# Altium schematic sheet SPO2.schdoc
size 297 x 209 mm; Symbol: Drawing-Symbol_A4; Company: 嘉立创EDA; Version: V1.0; Page Size: A4; @Project Name: OpenECG; @Update Date: 2026-05-02; @Create Date: 2026-05-02; Device: Drawing-Symbol_A4; @Board Name: Board2; @Page Name: P1; @Create Time: 22:49:49; @Page Count: 1; @Page No: 1; @Schematic Name: Schematic5; @Update Time: 22:49:49; @Assembly Variant: Basic; Border: 1; Title Block Position: 3; Size: A4; Width: 1170; Height: 825; Region Start: 1; X Region Count: 6; Y Region Count: 4; Blade Width: 10
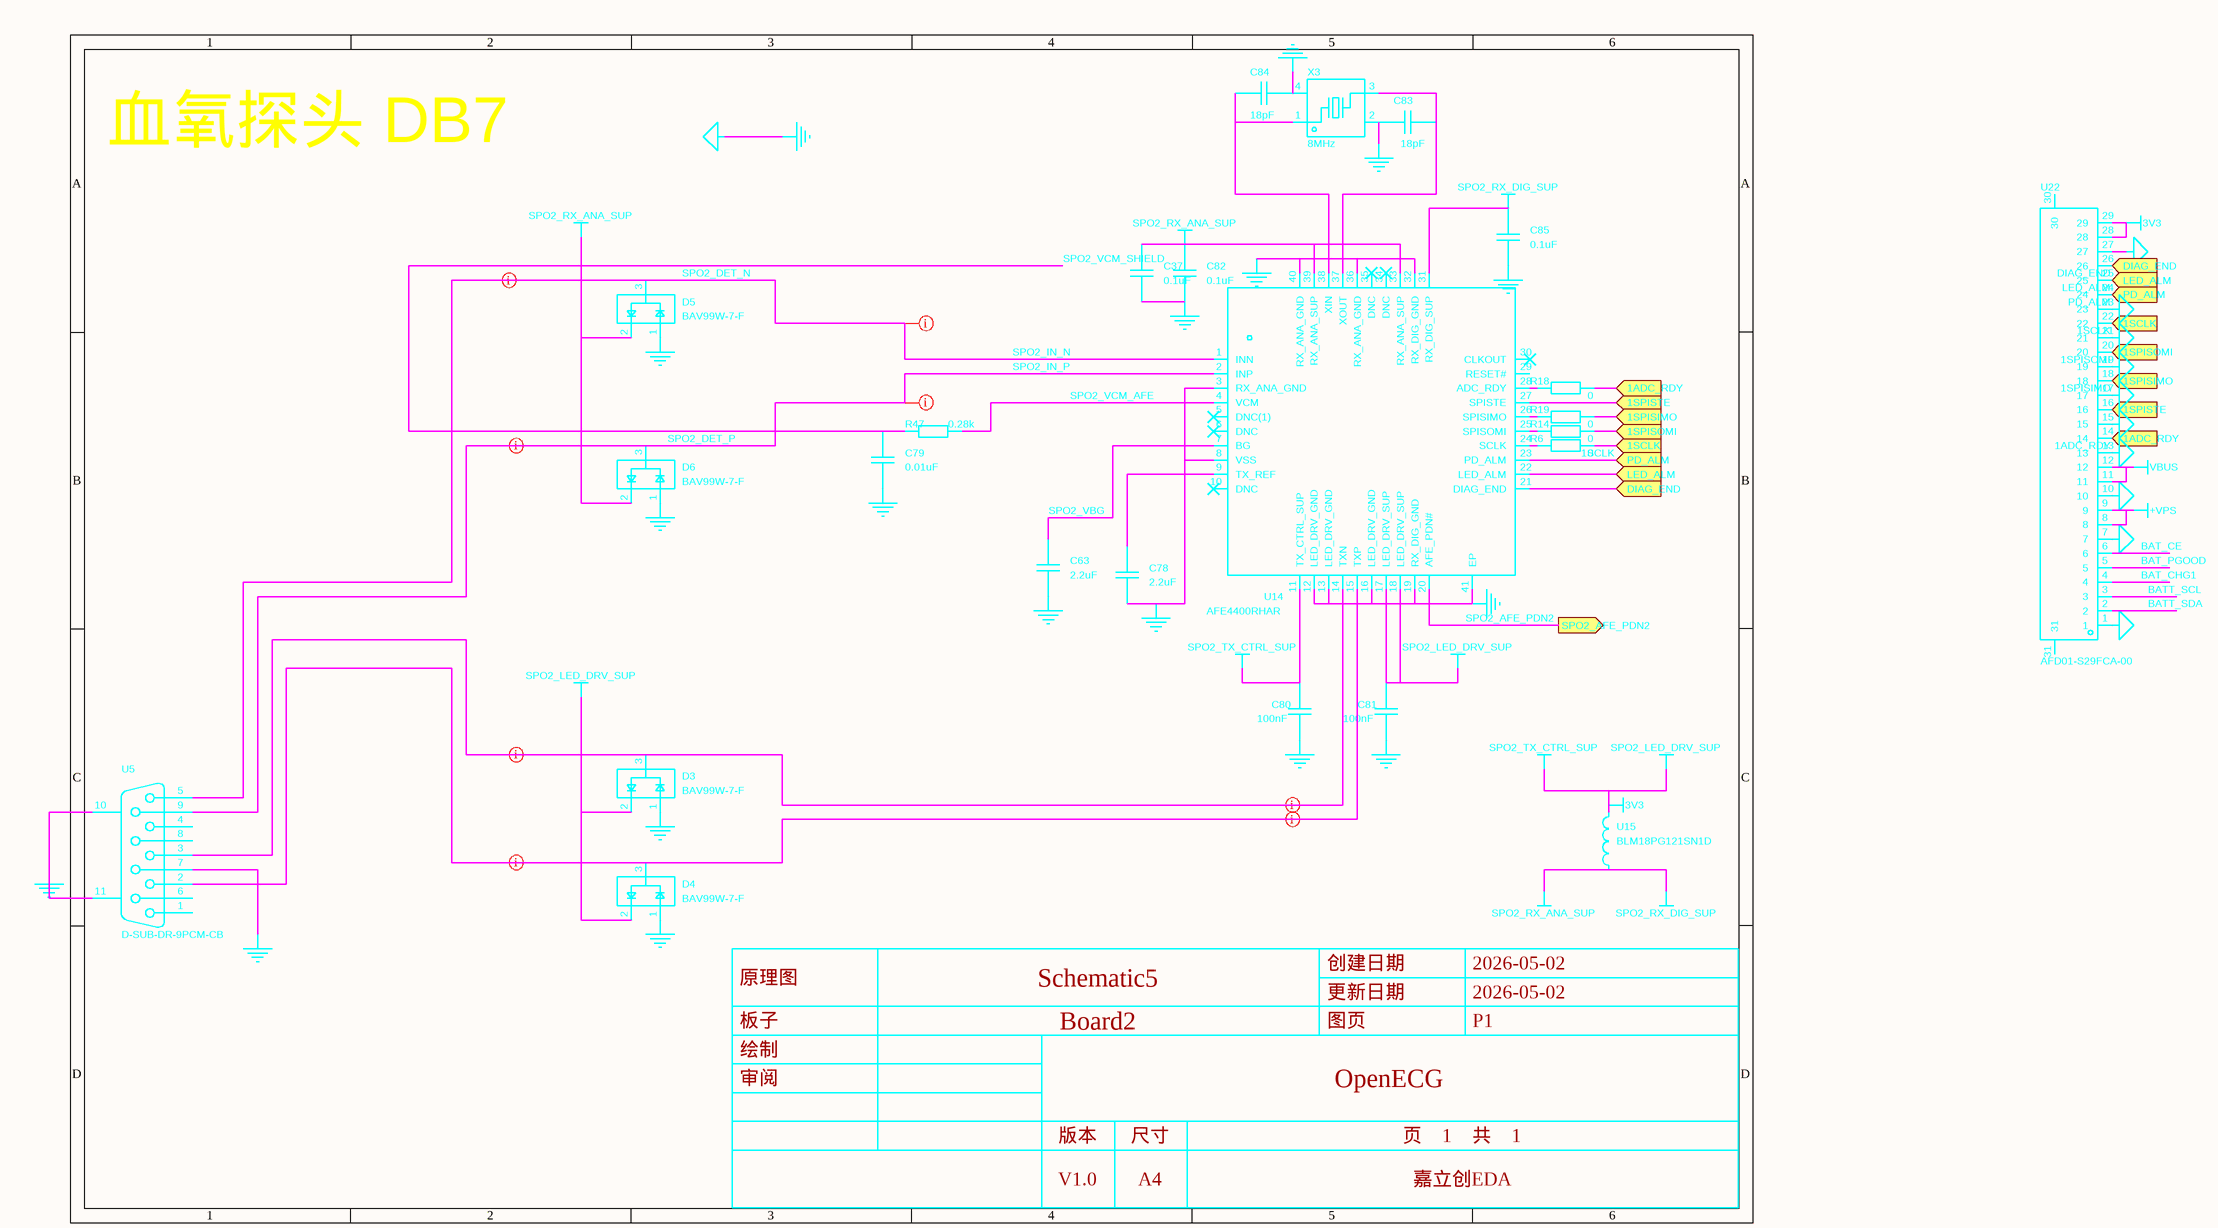
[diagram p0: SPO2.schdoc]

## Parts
C37  0.1uF  [R0603]
C63  2.2uF  [R0402]
C78  2.2uF  [R0402]
C79  0.01uF  [R0402]
C80  100nF  [C0603]
C81  100nF  [C0603]
C82  0.1uF  [R0603]
C83  18pF  [C0603]
C84  18pF  [C0603]
C85  0.1uF  [R0402]
D3  BAV99W-7-F  [SOT-323_L2.0-W1.3-P1.30-LS2.1-BR]
D4  BAV99W-7-F  [SOT-323_L2.0-W1.3-P1.30-LS2.1-BR]
D5  BAV99W-7-F  [SOT-323_L2.0-W1.3-P1.30-LS2.1-BR]
D6  BAV99W-7-F  [SOT-323_L2.0-W1.3-P1.30-LS2.1-BR]
R6  0  [R0603]
R14  0  [R0603]
R18  0  [R0603]
R19  0  [R0603]
R47  0.28k  [R0402]
U5  D-SUB-DR-9PCM-CB  [DB9-TH_D-SUB-DR-9PCM-CB]
U14  AFE4400RHAR  [VQFN-40_L6.0-W6.0-P0.50-TL-EP4.2]
U15  BLM18PG121SN1D  [R0402]
U22  AFD01-S29FCA-00  [FPC-SMD_29P-P0.50_JS_AFD01-S29FCA-00]
X3  8MHz  [CRYSTAL-SMD_4P-L3.2-W2.5-BL-1]

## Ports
1ADC_RDY (in), 1SCLK (in), 1SPISIMO (in), 1SPISOMI (in), 1SPISTE (in), DIAG_END (in), LED_ALM (in), PD_ALM (in), SPO2_AFE_PDN2 (out)

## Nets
3V3: C80.2 C81.2 D3.2 D4.2 U14.11(TX_CTRL_SUP) U14.17(LED_DRV_SUP) U14.18(LED_DRV_SUP) U15.2 U22.28 U22.29  [also labelled SPO2_LED_DRV_SUP, SPO2_TX_CTRL_SUP]
+VPS: U22.8 U22.9
AGND: C37.1 C63.1 C78.1 C79.1 C80.1 C81.1 C82.1 C83.1 C84.2 C85.1 D3.1 D4.1 D5.1 D6.1 U5.7 U5.10(MH1) U5.11(MH2) U14.3(RX_ANA_GND) U14.8(VSS) U14.12(LED_DRV_GND) U14.13(LED_DRV_GND) U14.16(LED_DRV_GND) U14.19(RX_DIG_GND) U14.32(RX_DIG_GND) U14.36(RX_ANA_GND) U14.40(RX_ANA_GND) U14.41(EP) U22.1 U22.7 U22.10 U22.13 U22.15 U22.17 U22.19 U22.21 U22.23 U22.27 X3.2(GND) X3.4(GND)  [also labelled GND]
SPO2_RX_ANA_SUP: C37.2 C82.2 C85.2 D5.2 D6.2 U14.31(RX_DIG_SUP) U14.33(RX_ANA_SUP) U14.39(RX_ANA_SUP) U15.1  [also labelled SPO2_RX_DIG_SUP]
VBUS: U22.11 U22.12
1ADC_RDY: R18.2 U22.14 ; port 1ADC_RDY
1SCLK: R6.2 U22.22 ; port 1SCLK
1SPISIMO: R19.2 U22.18 ; port 1SPISIMO
1SPISOMI: R14.2 U22.20 ; port 1SPISOMI
1SPISTE: U14.27(SPISTE) U22.16 ; port 1SPISTE
BAT_CE: U22.6
BAT_CHG1: U22.4
BAT_PGOOD: U22.5
BATT_SCL: U22.3
BATT_SDA: U22.2
DIAG_END: U14.21(DIAG_END) U22.26 ; port DIAG_END
LED_ALM: U14.22(LED_ALM) U22.25 ; port LED_ALM
PD_ALM: U14.23(PD_ALM) U22.24 ; port PD_ALM
SPO2_AFE_PDN2: U14.20(AFE_PDN#) ; port SPO2_AFE_PDN2
SPO2_DET_N: D5.3 U5.5 U14.1(INN)  [also labelled SPO2_IN_N]
SPO2_DET_P: D6.3 U5.9 U14.2(INP)  [also labelled SPO2_IN_P]
SPO2_VBG: C63.2 U14.7(BG)
SPO2_VCM_AFE: R47.2 U14.4(VCM)
SPO2_VCM_SHIELD: C79.2 R47.1
NetC78_2: C78.2 U14.9(TX_REF)
NetC83_2: C83.2 U14.37(XOUT) X3.3
NetC84_1: C84.1 U14.38(XIN) X3.1
NetD3_3: D3.3 U5.3 U14.14(TXN)
NetD4_3: D4.3 U5.2 U14.15(TXP)
NetR6_1: R6.1 U14.24(SCLK)
NetR14_1: R14.1 U14.25(SPISOMI)
NetR18_1: R18.1 U14.28(ADC_RDY)
NetR19_1: R19.1 U14.26(SPISIMO)

Not connected (* = marked no-connect by the designer): U5 1 4 6 8; U14 5(DNC(1))* 6(DNC)* 10(DNC)* 29(RESET#) 30(CLKOUT)* 34(DNC)* 35(DNC)*; U22 30 31

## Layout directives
differential pair; Symbol: Differential-Pairs-Flag; Device: Differential-Pairs-Flag: NetD3_3, NetD4_3, SPO2_DET_N, SPO2_DET_P

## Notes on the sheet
- 血氧探头 DB7

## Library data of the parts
C37 C63 C78-C85 = CAP_0603: Symbol: Capacitance; 3D Model: ac125912035d415993ca9572d50418b1; 3D Model Transform: 62.992,31.496,0,0,0,0,0,0,0; ConvertToPcb: yes; ModelName: C0603_L1.6-W0.8-H0.8
D3-D6 = BAV99W-7-F: 二极管配置:1对串联式;整流电流:150mA;直流反向耐压(Vr):75V;正向压降(Vf):1.25V@150mA;反向恢复时间(Trr):4ns;; Manufacturer: DIODES(美台); AddInBom: yes; ModelId: 6e43428e1fa34e53bcc36d788ead25670819f05c4eef4c71ace90d822a990e87; ModelName: SOT-323_L2.0-W1.3-H1.0-LS2.1-P1.30; ModelTransform: 78.74,82.677,0,90,0,0,0,0,0; Diode Configuration: 1对串联式; Pd - Power Dissipation: 200mW; Current - Rectified: 150mA; Voltage - DC Reverse(Vr): 75V; Non-Repetitive Peak Forward Surge Current: 2A; Reverse Leakage Current (Ir): 2.5uA@75V; Reverse Recovery Time (trr): 4ns; Operating Junction Temperature Range: -65℃~+150℃@(Tj)
R6 R14 R18 R19 = Res_0603: Symbol: 电阻; 3D Model: fc143cca1e79419f9cd78b61e9279f08; 3D Model Transform: 31.8897,63.7794,0,90,0,0,0,0,0; ConvertToPcb: yes
R47 = Res_0603: Symbol: 电阻; 3D Model: fc143cca1e79419f9cd78b61e9279f08; 3D Model Transform: 31.8897,63.7794,0,90,0,0,0,0,0; ConvertToPcb: yes; ModelName: R0603
U5 = D-SUB-DR-9PCM-CB: 公母:母;总PIN位数:9P;安装方式:弯插;排数:2;额定电流-信号脚:3A;工作温度:-50℃~+105℃;; Manufacturer: XUNPU(讯普); AddInBom: yes; ModelId: 6bcc70cbac914fdb99146137d8d8a1910819f05c4eef4c71ace90d822a990e87; ModelTransform: 1212.99,718.54187,0,0,0,0,-0.433,-246.299,-157.48; Gender: 母; Current Rating-Signal: 3A
U14 = AFE4400RHAR: 工作电压:2V~3.6V;工作电流:-;; Manufacturer: TI(德州仪器); AddInBom: yes; ModelId: 32089297f2ee4dc499e19e6e3ef127c20819f05c4eef4c71ace90d822a990e87; ModelTransform: 236.299,236.299,0,0,0,0,0,0,0; Resolution(Bits): 22位; S/N Ratio: 95dB; Clock Frequency: 4MHz；8MHz; Voltage Reference Value: 0.75V; Quiescent Current (Iq): 3uA; Interface: SPI
U15 = BLM18PG121SN1D: 标称阻抗@测试频率:120Ω@100MHz;误差:±25%;直流电阻(RDC):50mΩ;; Manufacturer: muRata(村田); Symbol: BLM18PG121SN1D_C14709; 3D Model: 2bc5ec593d464d6ba9807aec0b5673c2; 3D Model Transform: 62.992,31.496,0,180,0,0,0.094,0.629,0; Tolerance: ±25%; DC Resistance: 50mΩ; Current Rating: 2A; Circuits: 1; AddInBom: yes; ModelName: L0603_L1.6-W0.8-H0.5_BEAD
U22 = AFD01-S29FCA-00: 锁定特性:翻盖式;触点类型:下接;触点数量:29P;间距:0.5mm;安装方式:卧贴;; Manufacturer: JS(钜硕电子); AddInBom: yes; ModelId: d3d70d81697947e89ddc2db5d0f11f510819f05c4eef4c71ace90d822a990e87; ModelTransform: 783.463,240.157,0,0,0,0,-0.002,71.104,0; Locking Feature: 翻盖式; Number of Contacts: 29P; Pitch: 0.5mm
X3 = XL2EL89COI-111YLC-8M: 晶振类型:贴片晶振;频率:8MHz;常温频差:±10ppm;负载电容:12pF;频率稳定度:±20ppm;; Manufacturer: YXC(扬兴晶振); AddInBom: yes; ModelId: 4495b492a02c4f389e505ec8ae3aaf1b0819f05c4eef4c71ace90d822a990e87; ModelTransform: 125.984,98.425,0,0,0,0,0,0,0; Normal temperature Frequency Tolerance: ±10ppm; Load Capacitance: 12pF; Frequency Stability: ±20ppm; Equivalent Series Resistance(ESR): 150Ω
